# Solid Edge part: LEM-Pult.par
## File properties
Author: heha
Template: Normal.par
Last saved by: heha
Revision: 5
Application: Solid Edge
Genauigkeit: 0,990
Teilflächenrmatvorlage: Model Default
Coef. of Thermal Exp: 0.0
Thermal Conductivity: 0.0
Specific Heat: 0.0
Modulus of Elasticity: 0.0
Poission's Ratio: 0.0
Yield Stress: 0.0
Ultimate Stress: 0.0
Elongation: 0.0
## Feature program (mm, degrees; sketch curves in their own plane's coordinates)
sketch for "unnamed Protrusion 1" plane through (0, 0, 0) normal (0, -1, 0) x-axis (1, 0, 0)
  line (-13.1244, 0) -> (-13.1244, 4)
  line (-13.1244, 4) -> (-11.3923, 5)
  line (-11.3923, 5) -> (-10.5923, 3.6144)
  line (-10.5923, 3.6144) -> (10.1923, 15.6144)
  line (10.1923, 15.6144) -> (9.3923, 17)
  line (9.3923, 17) -> (11.1244, 18)
  line (11.1244, 18) -> (13.1244, 14.5359)
  line (13.1244, 14.5359) -> (13.1244, 0)
  line (13.1244, 0) -> (5.7, 0)
  line (5.7, 0) -> (5.7, -1.2)
  line (5.7, -1.2) -> (-5.7, -1.2)
  line (-5.7, -1.2) -> (-5.7, 0)
  line (-5.7, 0) -> (-13.1244, 0)
  dimension (linear) = 5.7
  dimension (linear) = 5.7
  dimension (linear) = 13.1244
  dimension (linear) = 13.1244
  dimension (linear) = 10.5923
  dimension (linear) = 11.3923
extrude "unnamed Protrusion 1" add finite 61 symmetric
sketch for "Schlüsselraum_Profile_Plane1" plane through (0, 0, 3) normal (0, 0, 1) x-axis (1, 0, 0)
  line (0, 10.5) -> (13.1244, 10.5)
  line (13.1244, 10.5) -> (13.1244, -10.5)
  line (13.1244, -10.5) -> (0, -10.5)
  arc centre (0, 0) radius 10.5 from (0, 10.5) to (0, -10.5) ccw
extrude "Schlüsselraum_Profile_Plane1" cut through along +normal  Distance = 3 mm
sketch for "Loch6" plane through (0, 0, 3) normal (0, 0, 1) x-axis (0, 1, 0)
  hole centre (0, 0) bore radius 3.1
hole "Loch6" diameter 6.2 through
sketch for "Bohrung_2" plane through (-0.2, 0, 9.6144) normal (-0.5, 0, 0.866025) x-axis (0, -1, 0)
  hole centre (26.8, 0) bore radius 1.3
hole "Bohrung_2" diameter 2.6 finite
sketch for "unnamed Hole 1" plane through (-0.2, 0, 9.6144) normal (-0.5, 0, 0.866025) x-axis (0, -1, 0)
  hole centre (-26.8, 0) bore radius 1.3
  dimension (linear) = 26.8
hole "unnamed Hole 1" finite
pattern "unnamed Pattern 1" of "Bohrung_2", "unnamed Hole 1"
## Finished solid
Body 1: solid body, 27 faces, 66 edges, 40 vertices.
  Faces by surface: plane 23, cylinder 4
  Edges by curve: line 58, circle 7, ellipse 1
Bounding box of the edges (mm): 26.249 x 61.000 x 19.200, from (-13.1244, -30.5, -1.2) to (13.1244, 30.5, 18).
Cylindrical faces by radius (mm): R1.3 x2, R3.1 x1, R10.5 x1
Planar faces by outward normal: +x 2, +y 2, +z 1, -x 2, -y 2, -z 3, oblique 11
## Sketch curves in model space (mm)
line (-5, 2.8868, 3) -> (0, 5.7735, 3)
line (0, 5.7735, 3) -> (5, 2.8868, 3)
line (5, 2.8868, 3) -> (5, -2.8868, 3)
line (5, -2.8868, 3) -> (0, -5.7735, 3)
line (0, -5.7735, 3) -> (-5, -2.8868, 3)
line (-5, -2.8868, 3) -> (-5, 2.8868, 3)
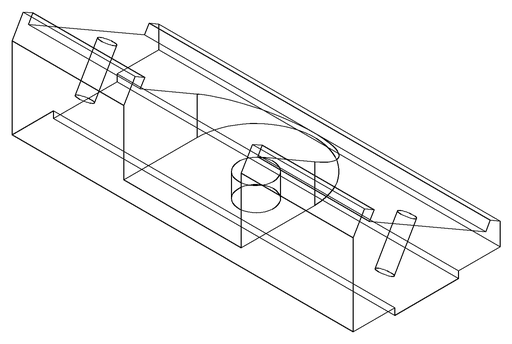
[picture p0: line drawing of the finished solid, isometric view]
